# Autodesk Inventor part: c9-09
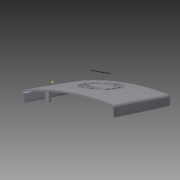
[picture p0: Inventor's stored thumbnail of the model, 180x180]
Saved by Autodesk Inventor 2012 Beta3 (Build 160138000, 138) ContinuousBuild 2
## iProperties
Created: 2010-12
Part Number: c9-09
Material: Default
Document SubType Name: Modeling
Designer: Beta-8540w
Density: 1 g/cm^3
Author: Beta-8540w
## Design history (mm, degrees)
sketch "Sketch1"
  geometry: L1 (-60, -12)-(60, -12); L2 (60, -12)-(60, 12); L3 (60, 12)-(-60, 12); L4 (-60, 12)-(-60, -12); A1 r 350 centre (0, -332.819) between (60, 12) and (-60, 12); A2 r 350 centre (0, 332.819) between (-60, -12) and (60, -12); 3 further points
  constraints: 8 end point, 4 point on circle, 2 centre point, 2 midpoint, 2 parallel, 1 equal radius, 1 horizontal, 1 horizontal alignment, 1 perpendicular, 1 vertical alignment
  dimensions: "d0" = 120 distance of L3.end L2.end; "d1" = 24 distance of L2.end L1.end; "d2" = 350 radius of A1
workplane "Work Plane4"
sketch "Sketch5"
  geometry: L1 (-60, 12)-(-60, -12) reference; L2 (60, -12)-(60, 12) reference; L3 (-58, 10.314)-(-58, -10.314); L4 (58, -10.314)-(58, 10.314); A1 r 350 centre (0, 332.819) between (-60, -12) and (60, -12) reference; A2 r 350 centre (0, -332.819) between (60, 12) and (-60, 12) reference; A3 r 348 centre (0, 332.819) between (-58, -10.314) and (58, -10.314); A4 r 348 centre (0, -332.819) between (58, 10.314) and (-58, 10.314); 1 further point
  constraints: 4 end point, 4 point on circle, 2 centre point, 3 other
  dimensions: "d37" = 2 distance between parallel lines of L2 L4
sketch "Sketch6"
  geometry: L1 (-60, 0)-(60, 0); L2 (60, 0)-(58.843, 22.085); L3 (-60, 0)-(-58.779, 23.307); A1 r 691.758 centre (630.81, -36.204) between (-60, 0) and (-58, -100); A2 r 691.758 centre (-630.81, -36.204) between (58, -100) and (60, 0); 1 further point
  constraints: 6 end point, 4 point on circle, 2 centre point, 2 tangent, 1 horizontal
  dimensions: "d53" = 87 deg angle of L1 L3; "d54" = 87 deg angle of L1 L2 (= d53)
sketch "Sketch7"
  geometry: L1 (17.181, 0)-(12, 0) reference; L2 (15.181, -100)-(10.314, -100) reference; L3 (17.181, 0)-(16.768, 11.838); A1 r 911.322 centre (-893.585, -31.805) between (15.181, -100) and (17.181, 0); 1 further point
  constraints: 2 end point, 2 point on circle, 1 centre point, 1 tangent
  dimensions: "d56" = 88 deg angle of L1 L3
feature "LoftSrf2" sketch "Sketch5", "Sketch6", "Sketch7" dims "d57" = 0, "d58" = 90 deg, "d59" = 0, "d60" = 90 deg, "d61" = 0, "d62" = 90 deg, "d63" = 0, "d64" = 90 deg, "d65" = 0, "d66" = 90 deg
sketch "Sketch2"
  geometry: L1 (-75, -16)-(75, -16); L2 (-75, -60)-(75, -60); A1 r 183.781 centre (0, -183.781) between (75, -16) and (-75, -16); 2 further points
  constraints: 4 end point, 3 point on circle, 1 centre point, 1 coincident, 1 horizontal, 1 parallel
  dimensions: "d5" = 16 distance from line of point (0, 0) L1; "d7" = 60 distance from line of point (0, 0) L2; "d55" = 150 distance of L1.start L1.end
feature "RevolutionSrf1" sketch "Sketch2" dims angle "d8" = 40 deg
patch "Boundary Patch1" dims "d13" = 0, "d67" = 0, "d68" = 0, "d69" = 0, "d70" = 0
workplane "Work Plane1"
sketch "Sketch3"
  geometry: L1 (52, -85)-(52, -73); L2 (38, -73)-(38, -85); A1 r 7 centre (45, -73) between (52, -73) and (38, -73); A2 r 7 centre (45, -85) between (38, -85) and (52, -85); 1 further point
  constraints: 4 end point, 4 point on circle, 4 tangent, 2 centre point, 1 parallel, 1 vertical
  dimensions: "d15" = 12 distance of L1.start L1.end; "d16" = 7 radius of A1; "d50" = 45 horizontal distance of A1.centre point (0, 0); "d51" = 85 vertical distance of point (0, 0) A2.centre
extrude_surface "ExtrusionSrf2" sketch "Sketch3" dims "d19" = 14, "d20" = 5 deg
pattern_linear "Rectangular Pattern1" dims "d23" = 90
workplane "Work Plane2"
feature "Sculpt1"
sketch "Sketch4"
  geometry: L1 (-24.5, 6)-(24.5, 6); L2 (27.5, 3)-(27.5, -3); L3 (24.5, -6)-(-24.5, -6); L4 (-27.5, -3)-(-27.5, 3); A1 r 3 centre (-24.5, 3) between (-24.5, 6) and (-27.5, 3); A2 r 3 centre (24.5, 3) between (27.5, 3) and (24.5, 6); A3 r 3 centre (24.5, -3) between (24.5, -6) and (27.5, -3); A4 r 3 centre (-24.5, -3) between (-27.5, -3) and (-24.5, -6); 6 further points
  constraints: 8 end point, 8 point on circle, 8 tangent, 6 point on line, 4 centre point, 3 equal radius, 2 midpoint, 2 parallel, 1 horizontal, 1 horizontal alignment, 1 perpendicular, 1 vertical alignment
  dimensions: "d28" = 55 distance of point (27.5, -6) point (-27.5, -6); "d29" = 12 distance of point (27.5, 6) point (27.5, -6); "d30" = 3 radius of A1
extrude_surface "ExtrusionSrf6" sketch "Sketch4" dims "d31" = 14, "d32" = 45 deg
patch "Boundary Patch2" dims "d33" = 0, "d34" = 0
fillet "Fillet1" dims "d79" = 4, "d80" = 3, "d81" = 1
feature "Sculpt2"
node "Splitting Plane 1"
shell "Shell1" dims "d83" = 2
split "Split1"
  body "Solid1"
feature "Lip1" dims "d171" = 1, "d172" = 1, "d173" = 0, "d174" = 0, "d175" = 0, "d176" = 0
feature "Lip2" dims "d177" = 1, "d178" = 1, "d179" = 0, "d180" = 0, "d181" = 0, "d182" = 0.5
split "Split3"
  node "Back"
sketch "Sketch9"
  geometry: L1 (50.167, -73)-(50.167, -85) reference; L2 (39.833, -85)-(39.833, -73) reference; L3 (45, -73)-(45, -85); L4 (45, -85)-(39.833, -85); A1 r 5.167 centre (45, -73) between (50.167, -73) and (39.833, -73) reference; A2 r 5.167 centre (45, -85) between (39.833, -85) and (50.167, -85) reference; 5 further points
  constraints: 4 end point, 1 horizontal, 1 midpoint, 1 parallel, 1 perpendicular, 1 vertical, 3 other
  dimensions: "d86" = 90 distance of point (45, -79) point (-45, -79); "d89" = 40 distance of point (45, -79) point (45, -39)
  node "Projected Loop1"
feature "Boss1" dims "d92" = 0, "d93" = 0, "d94" = 7, "d95" = 2, "d96" = 0.5, "d97" = 6, "d98" = 1.25, "d99" = 3.5, "d100" = 2.5 deg, "d101" = 2.5 deg, "d102" = 2.5 deg, "d103" = 2.5 deg, "d104" = 90 deg, "d107" = 2, "d108" = 2, "d109" = 10, "d110" = 0, "d111" = 10 deg, "d112" = 2.5 deg, "d113" = 0, "d114" = 0, "d115" = 0, "d116" = 360 deg
feature "Boss2" dims "d117" = 3, "d118" = 0, "d119" = 6, "d120" = 3, "d121" = 9.5, "d122" = 2 deg, "d123" = 1 deg, "d126" = 2, "d127" = 2, "d128" = 10, "d129" = 0, "d130" = 10 deg, "d131" = 2.5 deg, "d132" = 0, "d133" = 0, "d134" = 0, "d135" = 360 deg
workplane "Work Plane6"
sketch "Sketch10"
  geometry: L1 (24, -85)-(-24, -85); L2 (-30, -79)-(-30, -51); L3 (-24, -45)-(24, -45); L4 (30, -51)-(30, -79); L5 (54.344, -100)-(-54.344, -100) reference; A1 r 6 centre (-24, -51) between (-24, -45) and (-30, -51); A2 r 6 centre (24, -51) between (30, -51) and (24, -45); A3 r 6 centre (24, -79) between (24, -85) and (30, -79); A4 r 6 centre (-24, -79) between (-30, -79) and (-24, -85); 5 further points
  constraints: 8 end point, 8 point on circle, 8 tangent, 6 point on line, 4 centre point, 3 equal radius, 2 parallel, 1 horizontal, 1 midpoint, 1 perpendicular, 1 vertical alignment
  dimensions: "d137" = 60 distance of point (-30, -45) point (30, -45); "d138" = 40 distance of point (-30, -85) point (-30, -45); "d139" = 15 distance between parallel lines of L5 L1; "d141" = 6 radius of A2
feature "Rest1" sketch "Sketch10" dims "d142" = 5, "d143" = 0, "d144" = 0, "d145" = 0, "d146" = 2 deg, "d147" = 2 deg, "d148" = 2
feature "Rule Fillet1" dims "d149" = 2, "d150" = 1
workplane "Work Plane7"
sketch "Sketch11" dims "d154" = 16, "d155" = 8, "d161" = 10, "d168" = 10
  geometry: L1 (-13, -39.858)-(-13, -90.142); L2 (-25.187, -85)-(29.449, -85); L3 (0, -39.858)-(0, -90.142); L4 (13, -39.858)-(13, -90.142); L5 (-25.187, -77)-(29.449, -77); L6 (-25.187, -69)-(29.449, -69); L7 (-25.187, -61)-(29.449, -61); L8 (-25.187, -53)-(29.449, -53); L9 (-25.187, -45)-(29.449, -45); C1 r 22.5 at (0, -65); 3 further points; 1 other entity
  constraints: 18 end point, 2 coincident, 2 vertical, 1 centre point, 1 horizontal, 1 midpoint, 1 perpendicular, 1 vertical alignment, 23 other
  dimensions: "d152" = 45 diameter of C1; "d153" = 65 distance of point (0, 0) C1.centre; "d158" = 13 distance of L1.start L3.start; "d165" = 8 distance of L2.start L5.start; "d170" = 4 distance from line of L7 point (0, -65)
feature "Grill1" sketch "Sketch11" dims "d185" = 2, "d186" = 0, "d187" = 1, "d188" = 2, "d189" = 0, "d190" = 1, "d191" = 0.5, "d192" = 0, "d193" = 2, "d194" = 1, "d195" = 0, "d196" = 0, "d197" = 88.84493
sketch "Sketch12"
  geometry: L1 (-12.481, -61.203)-(12.401, -61.203); L2 (12.401, -61.203)-(12.401, -68.714); L3 (12.401, -68.714)-(-12.481, -68.714); L4 (-12.481, -68.714)-(-12.481, -61.203); 1 further point
  constraints: 2 other
body "Srf2"
body "Srf3"
body "Srf4"
body "Srf5"
body "Srf6"
body "Srf7"
body "Srf8"
body "Srf9"
body "Srf11"
feature "Stitch Surface1"
body "Srf12"
extrude_surface "ExtrusionSrf3"
extrude_surface "ExtrusionSrf4"
extrude_surface "ExtrusionSrf5"
node "Front"
node "Back - Top"
node "Back - Bottom"
other parameters: "d14" = -24, "d52" = -6, "d183" = 1, "d184" = 2
